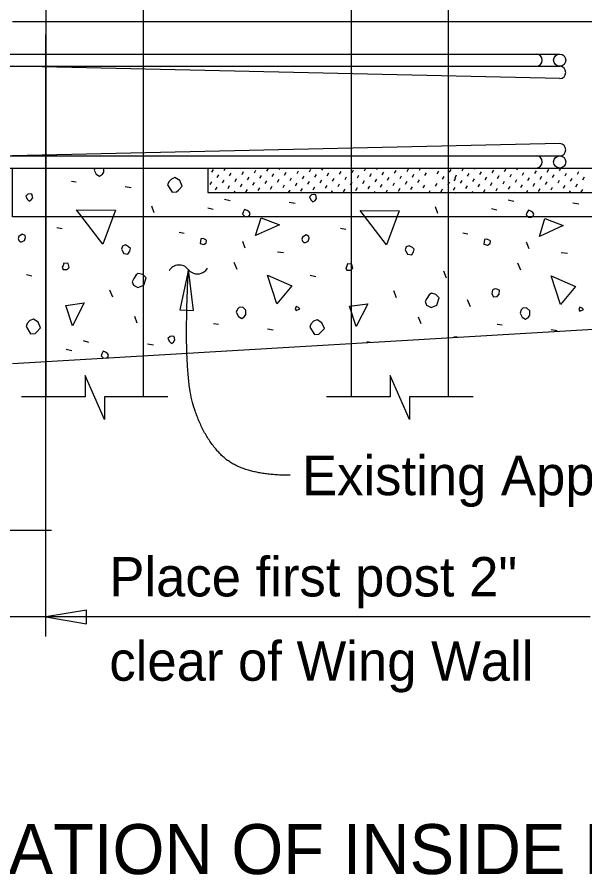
# Model space of a CAD drawing. Extents: x 1.5 to 68.7, y 0 to 31.
# Drawn here: x 7.561 to 10.468, y 8.928 to 13.319 of the extents above; entities that cross this region are included whole.
import ezdxf

# ---------------------------------------------------------------- set-up
doc = ezdxf.new("R2010")
doc.units = 0
for name, color, linetype in [('Dimension', 7, 'Continuous'), ('Miscellaneous', 7, 'Continuous'), ('Rebar', 7, 'Continuous'), ('TextStructures', 7, 'Continuous'), ('TrafBarrierConc', 7, 'Continuous')]:
    doc.layers.add(name, color=color, linetype=linetype)

msp = doc.modelspace()

# ---------------------------------------------------------------- linework, layer by layer
at = {"layer": 'Dimension'}
for p, q in [((7.7082, 10.1491), (7.7082, 13.2304)), ((10.4962, 10.2486), (7.1558, 10.2486))]:
    msp.add_line(p, q, dxfattribs=at)
for points in [[(8.438, 12.0275), (8.3942, 11.8209), (8.4647, 11.818)], [(7.7083, 10.2486), (7.9165, 10.2133), (7.9165, 10.2839)]]:
    msp.add_lwpolyline(points, close=True, dxfattribs=at)
for points in [[(8.3333, 11.3762), (8.008, 11.3762), (8.008, 11.2599), (7.9086, 11.4849), (7.9086, 11.3762), (7.5833, 11.3762)], [(9.8958, 11.3762), (9.5705, 11.3762), (9.5705, 11.2599), (9.4711, 11.4849), (9.4711, 11.3762), (9.1458, 11.3762)], [(7.7373, 10.6916), (7.087, 10.6916), (7.087, 10.5754), (6.9877, 10.8004), (6.9877, 10.6916), (6.3373, 10.6916)]]:
    msp.add_lwpolyline(points, dxfattribs=at)
for centre, start, end in [((8.3903, 11.9906), 38.2108, 149.938), ((8.484, 12.0643), 218.2108, 329.938)]:
    msp.add_arc(centre, 0.0596, start, end, dxfattribs=at)
msp.add_open_spline([(8.9586, 10.9737), (8.7125, 10.9737), (8.5074, 11.1744), (8.4117, 11.5165), (8.4379, 12.0275)], degree=2, dxfattribs=at)
at = {"layer": 'Miscellaneous'}
for p, q in [((8.5578, 12.5255), (8.5659, 12.5395)), ((8.6213, 12.5336), (8.6287, 12.5464)), ((8.649, 12.5059), (8.6571, 12.5199)), ((8.6848, 12.5417), (8.6875, 12.5464)), ((8.7125, 12.514), (8.7206, 12.528)), ((8.776, 12.5221), (8.7841, 12.5361)), ((8.8395, 12.5302), (8.8476, 12.5442)), ((8.8672, 12.5025), (8.8753, 12.5165)), ((8.903, 12.5383), (8.9076, 12.5464)), ((8.9307, 12.5106), (8.9388, 12.5246)), ((8.9942, 12.5187), (9.0023, 12.5327)), ((9.0577, 12.5268), (9.0658, 12.5408)), ((9.0854, 12.4991), (9.0935, 12.5131)), ((9.1211, 12.5349), (9.1278, 12.5464)), ((9.1488, 12.5073), (9.1569, 12.5212)), ((9.1846, 12.543), (9.1866, 12.5464)), ((9.2123, 12.5154), (9.2204, 12.5293)), ((9.2758, 12.5235), (9.2839, 12.5374)), ((9.3393, 12.5316), (9.3474, 12.5456)), ((9.367, 12.5039), (9.3751, 12.5179)), ((9.4028, 12.5397), (9.4067, 12.5464)), ((9.4305, 12.512), (9.4386, 12.526)), ((9.494, 12.5201), (9.5021, 12.5341)), ((9.5575, 12.5282), (9.5656, 12.5422)), ((9.5852, 12.5005), (9.5933, 12.5145)), ((9.621, 12.5363), (9.6268, 12.5464)), ((9.6487, 12.5086), (9.6568, 12.5226)), ((9.6845, 12.5444), (9.6856, 12.5464)), ((9.7122, 12.5167), (9.7203, 12.5307)), ((9.7757, 12.5248), (9.7838, 12.5388)), ((9.8392, 12.5329), (9.847, 12.5464)), ((9.8669, 12.5052), (9.875, 12.5192)), ((9.9026, 12.541), (9.9058, 12.5464)), ((9.9303, 12.5133), (9.9384, 12.5273)), ((9.9938, 12.5214), (10.0019, 12.5354)), ((10.0573, 12.5295), (10.0654, 12.5435)), ((10.085, 12.5018), (10.0931, 12.5158)), ((10.1208, 12.5376), (10.1259, 12.5464)), ((10.1485, 12.5099), (10.1566, 12.5239)), ((10.1843, 12.5457), (10.1847, 12.5464)), ((10.212, 12.518), (10.2201, 12.532)), ((10.2755, 12.5261), (10.2836, 12.5401)), ((10.339, 12.5342), (10.346, 12.5464)), ((10.3667, 12.5065), (10.3748, 12.5205)), ((10.4025, 12.5423), (10.4048, 12.5464)), ((10.4302, 12.5146), (10.4383, 12.5286)), ((7.8384, 12.4797), (7.8632, 12.4762)), ((8.5497, 12.462), (8.5578, 12.476)), ((8.5855, 12.4978), (8.5936, 12.5118)), ((8.6132, 12.4701), (8.6213, 12.4841)), ((8.6767, 12.4782), (8.6848, 12.4922)), ((8.7402, 12.4863), (8.7483, 12.5003)), ((8.7679, 12.4586), (8.776, 12.4726)), ((8.8037, 12.4944), (8.8118, 12.5084)), ((8.8314, 12.4667), (8.8395, 12.4807)), ((8.8949, 12.4748), (8.903, 12.4888)), ((8.9584, 12.4829), (8.9665, 12.4969)), ((8.9861, 12.4552), (8.9942, 12.4692)), ((9.0219, 12.491), (9.03, 12.505)), ((9.0496, 12.4634), (9.0577, 12.4773)), ((9.113, 12.4715), (9.1211, 12.4854)), ((9.1765, 12.4796), (9.1846, 12.4936)), ((9.24, 12.4877), (9.2481, 12.5017)), ((9.2677, 12.46), (9.2758, 12.474)), ((9.3035, 12.4958), (9.3116, 12.5098)), ((9.3312, 12.4681), (9.3393, 12.4821)), ((9.3947, 12.4762), (9.4028, 12.4902)), ((9.4582, 12.4843), (9.4663, 12.4983)), ((9.4859, 12.4566), (9.494, 12.4706)), ((9.5217, 12.4924), (9.5298, 12.5064)), ((9.5494, 12.4647), (9.5575, 12.4787)), ((9.6129, 12.4728), (9.621, 12.4868)), ((9.7399, 12.489), (9.748, 12.503)), ((9.7676, 12.4613), (9.7757, 12.4753)), ((9.7989, 12.4809), (9.807, 12.4949)), ((9.8034, 12.4971), (9.8115, 12.5111)), ((9.8311, 12.4694), (9.8392, 12.4834)), ((9.8945, 12.4775), (9.9026, 12.4915)), ((9.958, 12.4856), (9.9661, 12.4996)), ((9.9857, 12.4579), (9.9938, 12.4719)), ((10.0215, 12.4937), (10.0296, 12.5077)), ((10.0492, 12.466), (10.0573, 12.48)), ((10.1127, 12.4741), (10.1208, 12.4881)), ((10.1762, 12.4822), (10.1843, 12.4962)), ((10.2397, 12.4903), (10.2478, 12.5043)), ((10.2674, 12.4626), (10.2755, 12.4766)), ((10.3032, 12.4984), (10.3113, 12.5124)), ((10.3309, 12.4707), (10.339, 12.4847)), ((10.3944, 12.4788), (10.4025, 12.4928)), ((10.4579, 12.4869), (10.466, 12.5009)), ((8.1142, 12.4514), (8.1442, 12.4461)), ((8.5774, 12.4343), (8.5855, 12.4483)), ((8.6409, 12.4424), (8.649, 12.4564)), ((8.6725, 12.4214), (8.6767, 12.4287)), ((8.7044, 12.4505), (8.7125, 12.4645)), ((8.7321, 12.4228), (8.7402, 12.4368)), ((8.7956, 12.4309), (8.8037, 12.4449)), ((8.8591, 12.439), (8.8672, 12.453)), ((8.8926, 12.4214), (8.8949, 12.4253)), ((8.9226, 12.4471), (8.9307, 12.4611)), ((8.9514, 12.4214), (8.9584, 12.4334)), ((9.0138, 12.4276), (9.0219, 12.4415)), ((9.0772, 12.4357), (9.0854, 12.4497)), ((9.1407, 12.4438), (9.1488, 12.4578)), ((9.1715, 12.4214), (9.1765, 12.4301)), ((9.2042, 12.4519), (9.2123, 12.4659)), ((9.2319, 12.4242), (9.24, 12.4382)), ((9.2954, 12.4323), (9.3035, 12.4463)), ((9.3589, 12.4404), (9.367, 12.4544)), ((9.3917, 12.4214), (9.3947, 12.4267)), ((9.4224, 12.4485), (9.4305, 12.4625)), ((9.4505, 12.4214), (9.4582, 12.4348)), ((9.5136, 12.4289), (9.5217, 12.4429)), ((9.5771, 12.437), (9.5852, 12.451)), ((9.6406, 12.4451), (9.6487, 12.4591)), ((9.6706, 12.4214), (9.6764, 12.4314)), ((9.7041, 12.4532), (9.7122, 12.4672)), ((9.7318, 12.4255), (9.7399, 12.4395)), ((9.7953, 12.4336), (9.8034, 12.4476)), ((9.8587, 12.4417), (9.8669, 12.4557)), ((9.8907, 12.4214), (9.8945, 12.428)), ((9.9222, 12.4498), (9.9303, 12.4638)), ((9.9499, 12.4221), (9.958, 12.4361)), ((10.0134, 12.4302), (10.0215, 12.4442)), ((10.0769, 12.4383), (10.085, 12.4523)), ((10.1404, 12.4464), (10.1485, 12.4604)), ((10.1697, 12.4214), (10.1762, 12.4327)), ((10.2039, 12.4545), (10.212, 12.4685)), ((10.2316, 12.4268), (10.2397, 12.4408)), ((10.2951, 12.4349), (10.3032, 12.4489)), ((10.3586, 12.443), (10.3667, 12.457)), ((10.3898, 12.4214), (10.3944, 12.4293)), ((10.4221, 12.4511), (10.4302, 12.4651)), ((10.4498, 12.4234), (10.4579, 12.4374)), ((8.6233, 12.3878), (8.6516, 12.3807)), ((9.1127, 12.4214), (9.113, 12.422)), ((9.6118, 12.4214), (9.6129, 12.4233)), ((10.0764, 12.3842), (10.1047, 12.3772)), ((10.1109, 12.4214), (10.1127, 12.4246)), ((8.2627, 12.3171), (8.2503, 12.3506)), ((8.5367, 12.3436), (8.565, 12.3365)), ((8.9539, 12.3719), (8.9839, 12.3665)), ((9.7158, 12.3135), (9.7034, 12.3471)), ((9.9898, 12.34), (10.0181, 12.333)), ((10.407, 12.3683), (10.437, 12.363)), ((7.7642, 12.2428), (7.7907, 12.2375)), ((8.39, 12.2181), (8.4165, 12.2128)), ((9.2173, 12.2393), (9.2438, 12.234)), ((9.8431, 12.2145), (9.8696, 12.2092)), ((8.7294, 12.1367), (8.717, 12.1703)), ((10.1825, 12.1332), (10.1701, 12.1668)), ((8.8938, 12.1173), (8.9256, 12.1138)), ((10.3469, 12.1138), (10.3787, 12.1102)), ((8.6869, 12.0271), (8.6728, 12.0625)), ((10.1401, 12.0236), (10.1259, 12.059)), ((7.6086, 12.0024), (7.6369, 11.9953)), ((9.0617, 11.9989), (9.09, 11.9918)), ((9.76, 11.9829), (9.7458, 12.0183)), ((8.0506, 11.8857), (8.0364, 11.9211)), ((9.5037, 11.8822), (9.4895, 11.9175)), ((9.882, 11.8362), (9.8678, 11.8716)), ((8.1761, 11.7531), (8.1637, 11.7867)), ((9.6292, 11.7496), (9.6168, 11.7832)), ((8.5667, 11.7514), (8.5915, 11.7478)), ((8.8425, 11.7231), (8.8726, 11.7178)), ((10.0198, 11.7478), (10.0446, 11.7443)), ((10.2956, 11.7195), (10.3257, 11.7142)), ((7.8985, 11.663), (7.9268, 11.6559)), ((8.2291, 11.6471), (8.2591, 11.6418)), ((9.3516, 11.6594), (9.3698, 11.6549)), ((7.8119, 11.6188), (7.8402, 11.6117))]:
    msp.add_line(p, q, dxfattribs=at)
for points in [[(8.2082, 11.3761), (8.2082, 15.1963), (7.7082, 15.1963), (7.7082, 11.3761)], [(9.7707, 11.3761), (9.7707, 15.1963), (9.2707, 15.1963), (9.2707, 11.3761)], [(7.9551, 12.5363), (7.9657, 12.515), (7.9834, 12.5044), (7.9975, 12.515), (8.0046, 12.5256), (8.0046, 12.5464)], [(7.9585, 12.5464), (7.9551, 12.5363)], [(8.2601, 12.5464), (8.2609, 12.5451)], [(8.2609, 12.5451), (8.2638, 12.5464)], [(8.3316, 12.4602), (8.3546, 12.4231), (8.3776, 12.4249), (8.3864, 12.4337), (8.4059, 12.4532), (8.3935, 12.4832), (8.3688, 12.4974), (8.3511, 12.4903), (8.3369, 12.4762), (8.3316, 12.4602)], [(7.6121, 12.3878), (7.6228, 12.3772), (7.6334, 12.3842), (7.6404, 12.3948), (7.6369, 12.4125), (7.6281, 12.4143), (7.6157, 12.4125), (7.6051, 12.4019), (7.6121, 12.3878)], [(9.0653, 12.3842), (9.0759, 12.3736), (9.0865, 12.3807), (9.0935, 12.3913), (9.09, 12.409), (9.0812, 12.4107), (9.0688, 12.409), (9.0582, 12.3984), (9.0653, 12.3842)], [(9.8066, 12.4214), (9.8077, 12.4196), (9.8307, 12.4213), (9.8307, 12.4214)], [(7.9993, 12.1562), (7.8649, 12.333), (8.0647, 12.3312), (7.9993, 12.1562)], [(8.7258, 12.2994), (8.7382, 12.2976), (8.7506, 12.3029), (8.7541, 12.3135), (8.7488, 12.3224), (8.7382, 12.3294), (8.7258, 12.3347), (8.7188, 12.3206), (8.7152, 12.31), (8.7258, 12.2994)], [(9.4524, 12.1526), (9.318, 12.3294), (9.5178, 12.3277), (9.4524, 12.1526)], [(10.1789, 12.2958), (10.1913, 12.2941), (10.2037, 12.2994), (10.2072, 12.31), (10.2019, 12.3188), (10.1913, 12.3259), (10.1789, 12.3312), (10.1719, 12.3171), (10.1683, 12.3064), (10.1789, 12.2958)], [(8.7824, 12.2004), (8.8107, 12.2923), (8.9044, 12.2552), (8.7824, 12.2004)], [(10.2355, 12.1968), (10.2638, 12.2888), (10.3575, 12.2516), (10.2355, 12.1968)], [(7.5768, 12.1686), (7.5839, 12.1686), (7.598, 12.1756), (7.6033, 12.1915), (7.6015, 12.2004), (7.5874, 12.2074), (7.5697, 12.1968), (7.5662, 12.1862), (7.5697, 12.1756), (7.5768, 12.1686)], [(8.4978, 12.1597), (8.5172, 12.1544), (8.5296, 12.1633), (8.5314, 12.1756), (8.5279, 12.1792), (8.5137, 12.1862), (8.5013, 12.1845), (8.4996, 12.1721), (8.4978, 12.1597)], [(9.0299, 12.165), (9.037, 12.165), (9.0511, 12.1721), (9.0564, 12.188), (9.0546, 12.1968), (9.0405, 12.2039), (9.0228, 12.1933), (9.0193, 12.1827), (9.0228, 12.1721), (9.0299, 12.165)], [(9.9509, 12.1562), (9.9703, 12.1509), (9.9827, 12.1597), (9.9845, 12.1721), (9.981, 12.1756), (9.9668, 12.1827), (9.9544, 12.1809), (9.9527, 12.1686), (9.9509, 12.1562)], [(8.0983, 12.1244), (8.1071, 12.1085), (8.1283, 12.1049), (8.1372, 12.1208), (8.1407, 12.135), (8.1319, 12.1438), (8.116, 12.1526), (8.1001, 12.1473), (8.0947, 12.1314), (8.0983, 12.1244)], [(9.5514, 12.1208), (9.5602, 12.1049), (9.5814, 12.1014), (9.5903, 12.1173), (9.5938, 12.1314), (9.585, 12.1403), (9.5691, 12.1491), (9.5532, 12.1438), (9.5479, 12.1279), (9.5514, 12.1208)], [(7.796, 12.0271), (7.8172, 12.0271), (7.8278, 12.0377), (7.8225, 12.0572), (7.7995, 12.059), (7.796, 12.0484), (7.7907, 12.0395), (7.796, 12.0271), (7.7925, 12.0307)], [(9.2491, 12.0236), (9.2703, 12.0236), (9.2809, 12.0342), (9.2756, 12.0537), (9.2526, 12.0554), (9.2491, 12.0448), (9.2438, 12.036), (9.2491, 12.0236), (9.2456, 12.0271)], [(8.1563, 11.9467), (8.1793, 11.9344), (8.2094, 11.9467), (8.2217, 11.9839), (8.2041, 12.0015), (8.1811, 12.0069), (8.1705, 11.9998), (8.1581, 11.9803), (8.1493, 11.9644), (8.1563, 11.9467)], [(8.8902, 11.8521), (8.8425, 11.9989), (8.968, 11.9441), (8.8902, 11.8521)], [(10.3433, 11.8486), (10.2956, 11.9953), (10.4211, 11.9405), (10.3433, 11.8486)], [(9.6575, 11.8451), (9.6804, 11.8327), (9.7105, 11.8451), (9.7229, 11.8822), (9.7052, 11.8999), (9.6822, 11.9052), (9.6716, 11.8981), (9.6592, 11.8786), (9.6504, 11.8627), (9.6575, 11.8451)], [(9.9916, 11.9034), (10.0004, 11.8875), (10.0198, 11.8893), (10.0287, 11.9016), (10.0305, 11.9211), (10.0181, 11.9264), (10.0092, 11.9281), (9.9986, 11.9246), (9.9951, 11.9211), (9.9916, 11.9034)], [(7.8437, 11.739), (7.8101, 11.8433), (7.9038, 11.8557), (7.8437, 11.739)], [(8.6834, 11.8079), (8.694, 11.7867), (8.7117, 11.7761), (8.7258, 11.7867), (8.7329, 11.7973), (8.7329, 11.8185), (8.717, 11.8345), (8.6976, 11.8327), (8.6887, 11.8238), (8.6834, 11.8079)], [(8.9892, 11.8168), (9.0087, 11.8256), (9.0016, 11.8327), (8.9892, 11.838), (8.9839, 11.8256), (8.9892, 11.8168)], [(9.2968, 11.7355), (9.2632, 11.8398), (9.3569, 11.8521), (9.2968, 11.7355)], [(10.1365, 11.8044), (10.1471, 11.7832), (10.1648, 11.7726), (10.1789, 11.7832), (10.186, 11.7938), (10.186, 11.815), (10.1701, 11.8309), (10.1507, 11.8291), (10.1418, 11.8203), (10.1365, 11.8044)], [(10.4423, 11.8132), (10.4618, 11.8221), (10.4547, 11.8291), (10.4423, 11.8345), (10.437, 11.8221), (10.4423, 11.8132)], [(7.6068, 11.7355), (7.6298, 11.6983), (7.6528, 11.7001), (7.6616, 11.7089), (7.6811, 11.7284), (7.6687, 11.7584), (7.644, 11.7726), (7.6263, 11.7655), (7.6121, 11.7514), (7.6068, 11.7355)], [(9.0599, 11.7319), (9.0829, 11.6948), (9.1059, 11.6966), (9.1147, 11.7054), (9.1342, 11.7248), (9.1218, 11.7549), (9.0971, 11.769), (9.0794, 11.762), (9.0653, 11.7478), (9.0599, 11.7319)], [(8.3405, 11.6594), (8.3511, 11.6488), (8.3617, 11.6559), (8.3688, 11.6665), (8.3652, 11.6842), (8.3564, 11.686), (8.344, 11.6842), (8.3334, 11.6736), (8.3405, 11.6594)], [(9.8152, 11.6813), (9.8095, 11.6824), (9.7971, 11.6807), (9.7966, 11.6802)], [(8.0181, 11.5748), (8.0258, 11.5781), (8.0293, 11.5887), (8.024, 11.5976), (8.0134, 11.6046), (8.0011, 11.6099), (7.994, 11.5958), (7.9904, 11.5852), (8.0011, 11.5746)], [(8.0011, 11.5746), (8.0049, 11.574)]]:
    msp.add_lwpolyline(points, dxfattribs=at)
at = {"layer": 'Rebar'}
for p, q in [((6.704, 13.1297), (10.3395, 13.1297)), ((6.704, 13.0672), (10.3395, 13.0672)), ((10.3395, 13.0048), (7.5373, 13.0672)), ((10.3395, 12.6713), (7.5373, 12.6089)), ((6.704, 12.6089), (10.3395, 12.6089)), ((6.704, 12.5464), (10.3395, 12.5464))]:
    msp.add_line(p, q, dxfattribs=at)
for centre in [(10.3395, 13.0984), (10.3395, 12.5776)]:
    msp.add_circle(centre, 0.0312, dxfattribs=at)
for centre in [(10.2192, 13.0985), (10.3395, 13.036), (10.3395, 13.036), (10.3395, 12.6401), (10.2192, 12.5777)]:
    msp.add_arc(centre, 0.0312, 270, 90, dxfattribs=at)
at = {"layer": 'TrafBarrierConc'}
for p, q in [((7.5373, 13.2964), (10.5373, 13.2964)), ((6.5373, 12.5464), (12.2608, 12.5464)), ((8.5374, 12.5464), (8.5374, 12.4214)), ((8.5374, 12.4214), (12.2608, 12.4214)), ((7.5373, 11.5463), (11.7573, 11.7963))]:
    msp.add_line(p, q, dxfattribs=at)
msp.add_lwpolyline([(10.5373, 12.5464), (10.5373, 12.2964), (7.5373, 12.2964), (7.5373, 12.5464)], dxfattribs=at)

# ---------------------------------------------------------------- texts
at = {"layer": 'Dimension'}
msp.add_text('PARTIAL ELEVATION OF INSIDE FACE OF GUARDRAIL', height=0.256001, dxfattribs=at).set_placement((5.1193, 8.9321))
at = {"layer": 'TextStructures'}
for s, p in [('Existing Approach Slab', (9.0197, 10.8719)), ('Place first post 2"', (8.033, 10.3536)), ('clear of Wing Wall', (8.033, 9.922))]:
    msp.add_text(s, height=0.2016, dxfattribs=at).set_placement(p)

doc.saveas('drawing.dxf')
